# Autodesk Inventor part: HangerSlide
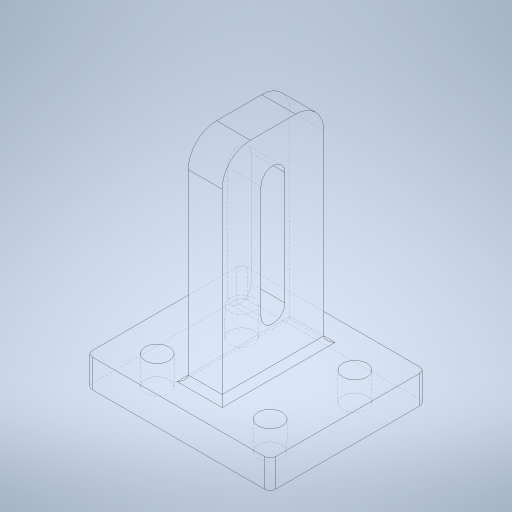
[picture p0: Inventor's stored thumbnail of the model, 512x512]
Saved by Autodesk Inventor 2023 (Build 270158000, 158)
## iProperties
Created: 2023-11
Part Number: HangerSlide
Material: Generic
Document SubType Name: Modeling
Designer: tornqvih
Density: 1 g/cm^3
Appearance: Default
Mass: 60.6554 g
Surface Area: 175.409 cm^2
Volume: 60.6554 cm^3
Author: tornqvih
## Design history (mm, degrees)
sketch "Sketch1"
  geometry: L1 (-32.5, 27.5)-(32.5, 27.5); L2 (32.5, 27.5)-(32.5, -27.5); L3 (32.5, -27.5)-(-32.5, -27.5); L4 (-32.5, -27.5)-(-32.5, 27.5); L5 (-32.5, 27.5)-(32.5, -27.5); L6 (32.5, 27.5)-(-32.5, -27.5); 1 further point
  constraints: 12 end point, 2 midpoint, 2 parallel, 1 horizontal, 1 perpendicular
  dimensions: "d4" = 65 distance of L1.start L1.end; "d5" = 55 distance of L3.end L1.start
extrude "Extrusion2" new body sketch "Sketch1" distance "d6" = 10; taper "d7" = 0 deg
sketch "Sketch2"
  geometry: L1 (10, 27.5)-(10, -27.5) reference; L2 (10, -18)-(85, -18); L3 (85, -18)-(85, 18); L4 (85, 18)-(10, 18); L5 (0, -27.5)-(10, -27.5) reference; L6 (-16.6, 0)-(99.6, 0) reference; 2 further points
  constraints: 6 end point, 3 perpendicular, 1 point on line, 1 symmetric about line
  dimensions: "d93" = 75 distance between parallel lines of L1 L3; "d96" = 36 distance between parallel lines of L2 L4
extrude "Extrusion3" join sketch "Sketch2" stored distance "d13" = 12; taper "d14" = 0 deg
sketch "Sketch3"
  geometry: L1 (-4.25, 69)-(-4.25, 29); L2 (4.25, 29)-(4.25, 69); L3 (18, 85)-(-18, 85) reference; L4 (-27.5, 10)-(27.5, 10) reference; L5 (0, -17)-(0, 102) reference; A1 r 4.25 centre (0, 69) between (4.25, 69) and (-4.25, 69); A2 r 4.25 centre (0, 29) between (-4.25, 29) and (4.25, 29); 2 further points; 1 other entity
  constraints: 4 end point, 4 point on circle, 4 tangent, 2 centre point, 2 point on line, 1 parallel, 1 other
  dimensions: "d15" = 8.5 distance between parallel lines of L2 L1; "d16" = 40 distance of A1.centre A2.centre; "d75" = 16 distance from line of L3 A1.centre
extrude "Extrusion4" cut sketch "Sketch3" distance "d20" = 12; taper "d21" = 0 deg
fillet "Fillet1" dims "d22" = 10
fillet "Fillet3" dims "d74" = 2
sketch "Sketch9"
  geometry: L1 (-45.5, 0)-(45.5, 0) reference; L2 (-30.5, 27.5)-(30.5, 27.5) reference; L3 (-32.5, -25.5)-(-32.5, 25.5) reference; L4 (0, -38.5)-(0, 38.5) reference; 5 further points
  constraints: 3 symmetric about line
  dimensions: "d92" = 40 distance of point (20, -15) point (-20, -15); "d94" = 30 distance of point (-20, -15) point (-20, 15)
hole "Hole3" sketch "Sketch9" at (-20, 15), (20, 15), (-20, -15), (20, -15) diameter "d85" = 8.5; stored, may be unused: countersink angle "d89" = 90 deg, drill point angle "d91" = 118 deg; dims "d86" = 6, "d87" = 4, "d88" = 2, "d90" = 8
fillet "Fillet4" dims "d95" = 2
body "Solid2"
